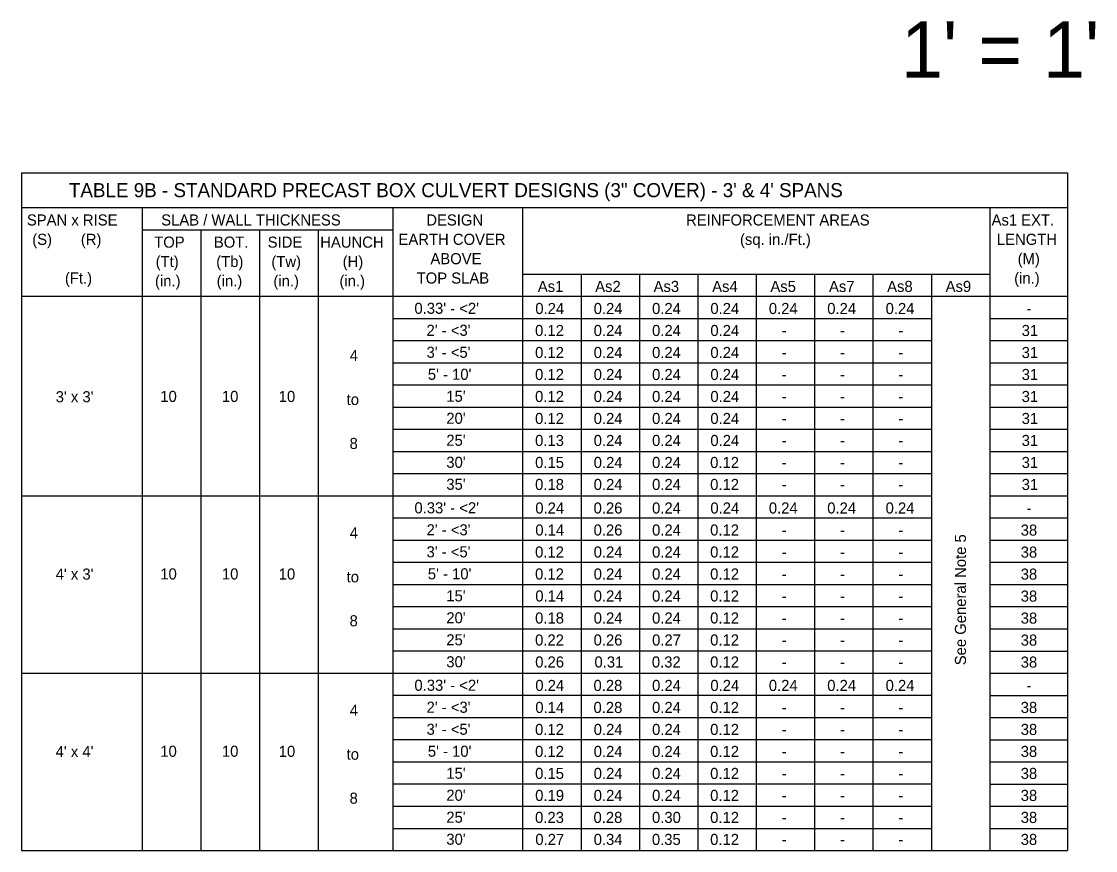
# Model space of a CAD drawing. Extents: x 10338.56 to 10340.78, y 76371.51 to 76372.62.
# Drawn here: x 10339.21 to 10339.821, y 76372.15 to 76372.621 of the extents above; entities that cross this region are included whole.
import ezdxf

# ---------------------------------------------------------------- set-up
doc = ezdxf.new("R2010")
doc.units = 0
doc.layers.add('Border', color=7, linetype='Continuous')
doc.layers.add('SheetBorder_dp', color=7, linetype='Continuous')

msp = doc.modelspace()

# ---------------------------------------------------------------- linework, layer by layer
at = {"layer": 'Border'}
for p, q in [((10339.21023, 76372.53475), (10339.80497, 76372.53475)), ((10339.21023, 76372.53475), (10339.21023, 76372.14953)), ((10339.80497, 76372.53475), (10339.80497, 76372.14953)), ((10339.21023, 76372.51488), (10339.80497, 76372.51488)), ((10339.27886, 76372.51488), (10339.27886, 76372.14958)), ((10339.42131, 76372.51488), (10339.42131, 76372.14958)), ((10339.49519, 76372.51488), (10339.49519, 76372.14958)), ((10339.76078, 76372.51488), (10339.76078, 76372.14958)), ((10339.27886, 76372.50228), (10339.42131, 76372.50228)), ((10339.31222, 76372.50228), (10339.31222, 76372.14958)), ((10339.34558, 76372.50228), (10339.34558, 76372.14958)), ((10339.37895, 76372.50228), (10339.37895, 76372.14958)), ((10339.49519, 76372.47713), (10339.76078, 76372.47713)), ((10339.52839, 76372.47713), (10339.52839, 76372.14958)), ((10339.56158, 76372.47713), (10339.56158, 76372.14958)), ((10339.59478, 76372.47713), (10339.59478, 76372.14958)), ((10339.62798, 76372.47713), (10339.62798, 76372.14958)), ((10339.66118, 76372.47713), (10339.66118, 76372.14958)), ((10339.66118, 76372.47713), (10339.66118, 76372.14958)), ((10339.69438, 76372.47713), (10339.69438, 76372.14958)), ((10339.72758, 76372.47713), (10339.72758, 76372.14958)), ((10339.21023, 76372.46453), (10339.80497, 76372.46453)), ((10339.42131, 76372.45193), (10339.72758, 76372.45193)), ((10339.76078, 76372.45191), (10339.80497, 76372.45191)), ((10339.42131, 76372.43933), (10339.72758, 76372.43933)), ((10339.76078, 76372.43931), (10339.80497, 76372.43931)), ((10339.42131, 76372.42673), (10339.72758, 76372.42673)), ((10339.76078, 76372.42671), (10339.80497, 76372.42671)), ((10339.42131, 76372.41413), (10339.72758, 76372.41413)), ((10339.76078, 76372.41411), (10339.80497, 76372.41411)), ((10339.42131, 76372.40153), (10339.72758, 76372.40153)), ((10339.76078, 76372.40151), (10339.80497, 76372.40151)), ((10339.42131, 76372.38893), (10339.72758, 76372.38893)), ((10339.76078, 76372.38891), (10339.80497, 76372.38891)), ((10339.42131, 76372.37633), (10339.72758, 76372.37633)), ((10339.76078, 76372.37631), (10339.80497, 76372.37631)), ((10339.42131, 76372.36373), (10339.72758, 76372.36373)), ((10339.76078, 76372.36371), (10339.80497, 76372.36371)), ((10339.21023, 76372.35113), (10339.72758, 76372.35113)), ((10339.76078, 76372.35111), (10339.80497, 76372.35111)), ((10339.42131, 76372.33853), (10339.72758, 76372.33853)), ((10339.76078, 76372.33851), (10339.80497, 76372.33851)), ((10339.42131, 76372.32593), (10339.72758, 76372.32593)), ((10339.76078, 76372.32591), (10339.80497, 76372.32591)), ((10339.42131, 76372.31333), (10339.72758, 76372.31333)), ((10339.76078, 76372.31331), (10339.80497, 76372.31331)), ((10339.42131, 76372.30073), (10339.72758, 76372.30073)), ((10339.76078, 76372.30071), (10339.80497, 76372.30071)), ((10339.42131, 76372.28813), (10339.72758, 76372.28813)), ((10339.76078, 76372.28811), (10339.80497, 76372.28811)), ((10339.42131, 76372.27553), (10339.72758, 76372.27553)), ((10339.76078, 76372.27551), (10339.80497, 76372.27551)), ((10339.42131, 76372.26293), (10339.72758, 76372.26293)), ((10339.76078, 76372.26291), (10339.80497, 76372.26291)), ((10339.21023, 76372.25033), (10339.72758, 76372.25033)), ((10339.76078, 76372.25031), (10339.80497, 76372.25031)), ((10339.42131, 76372.23773), (10339.72758, 76372.23773)), ((10339.76078, 76372.23771), (10339.80497, 76372.23771)), ((10339.42131, 76372.22513), (10339.72758, 76372.22513)), ((10339.76078, 76372.22511), (10339.80497, 76372.22511)), ((10339.42131, 76372.21253), (10339.72758, 76372.21253)), ((10339.76078, 76372.21251), (10339.80497, 76372.21251)), ((10339.42131, 76372.19993), (10339.72758, 76372.19993)), ((10339.76078, 76372.19991), (10339.80497, 76372.19991)), ((10339.42131, 76372.18733), (10339.72758, 76372.18733)), ((10339.76078, 76372.18731), (10339.80497, 76372.18731)), ((10339.42131, 76372.17473), (10339.72758, 76372.17473)), ((10339.76078, 76372.17471), (10339.80497, 76372.17471)), ((10339.42131, 76372.16213), (10339.72758, 76372.16213)), ((10339.76078, 76372.16211), (10339.80497, 76372.16211)), ((10339.21023, 76372.14953), (10339.80497, 76372.14953))]:
    msp.add_line(p, q, dxfattribs=at)

# ---------------------------------------------------------------- texts
for s, p in [('SPAN x RISE', (10339.21331, 76372.50472)), ('DESIGN', (10339.44041, 76372.50472)), ('REINFORCEMENT AREAS', (10339.58809, 76372.50472)), ('(S)       (R)', (10339.21636, 76372.49372)), ('(sq. in./Ft.)', (10339.61878, 76372.49372)), ('TOP', (10339.28569, 76372.49212)), ('BOT.', (10339.31962, 76372.49212)), ('SIDE', (10339.35021, 76372.49212)), ('HAUNCH', (10339.3801, 76372.49212)), ('EARTH COVER', (10339.42462, 76372.49372)), ('ABOVE', (10339.44276, 76372.48272)), ('(Tt)', (10339.28653, 76372.48112)), ('(Tb)', (10339.32096, 76372.48112)), ('(Tw)', (10339.35232, 76372.48112)), ('(H)', (10339.39285, 76372.48112)), ('(Ft.)', (10339.23493, 76372.47172)), ('(in.)', (10339.28614, 76372.47012)), ('(in.)', (10339.32123, 76372.47012)), ('(in.)', (10339.35347, 76372.47012)), ('(in.)', (10339.39104, 76372.47012)), ('TOP SLAB', (10339.43493, 76372.47172)), ("0.33' - <2'", (10339.43366, 76372.45452)), ('0.24', (10339.50239, 76372.45441)), ('0.24', (10339.53559, 76372.45441)), ('0.24', (10339.56879, 76372.45441)), ('0.24', (10339.60194, 76372.45441)), ('0.24', (10339.63518, 76372.45441)), ('0.24', (10339.66838, 76372.45441)), ('0.24', (10339.70157, 76372.45441)), ('-', (10339.7817, 76372.45441)), ("2' - <3'", (10339.44056, 76372.44202)), ('0.12', (10339.50226, 76372.44191)), ('0.24', (10339.53559, 76372.44191)), ('0.24', (10339.56879, 76372.44191)), ('0.24', (10339.60194, 76372.44191)), ('31', (10339.77893, 76372.44191)), ('-', (10339.64245, 76372.44191)), ('-', (10339.67566, 76372.44191)), ('-', (10339.70885, 76372.44191)), ('4', (10339.39689, 76372.42773)), ("3' - <5'", (10339.44056, 76372.42952)), ('0.12', (10339.50226, 76372.42941)), ('0.24', (10339.53559, 76372.42941)), ('0.24', (10339.56879, 76372.42941)), ('0.24', (10339.60194, 76372.42941)), ('31', (10339.77893, 76372.42941)), ('-', (10339.64245, 76372.42941)), ('-', (10339.67566, 76372.42941)), ('-', (10339.70885, 76372.42941)), ("5' - 10'", (10339.44128, 76372.41702)), ('0.12', (10339.50226, 76372.41691)), ('0.24', (10339.53559, 76372.41691)), ('0.24', (10339.56879, 76372.41691)), ('0.24', (10339.60194, 76372.41691)), ('31', (10339.77893, 76372.41691)), ('-', (10339.64245, 76372.41691)), ('-', (10339.67566, 76372.41691)), ('-', (10339.70885, 76372.41691)), ('10', (10339.28917, 76372.40446)), ('10', (10339.32421, 76372.40446)), ('10', (10339.3565, 76372.40441)), ("15'", (10339.45179, 76372.40452)), ('0.12', (10339.50226, 76372.40441)), ('0.24', (10339.53559, 76372.40441)), ('0.24', (10339.56879, 76372.40441)), ('0.24', (10339.60194, 76372.40441)), ('31', (10339.77893, 76372.40441)), ('to', (10339.39511, 76372.40273)), ('-', (10339.64245, 76372.40441)), ('-', (10339.67566, 76372.40441)), ('-', (10339.70885, 76372.40441)), ("20'", (10339.45179, 76372.39202)), ('0.12', (10339.50226, 76372.39191)), ('0.24', (10339.53559, 76372.39191)), ('0.24', (10339.56879, 76372.39191)), ('0.24', (10339.60194, 76372.39191)), ('31', (10339.77893, 76372.39191)), ('-', (10339.64245, 76372.39191)), ('-', (10339.67566, 76372.39191)), ('-', (10339.70885, 76372.39191)), ("25'", (10339.45179, 76372.37952)), ('0.13', (10339.50226, 76372.37941)), ('0.24', (10339.53559, 76372.37941)), ('0.24', (10339.56879, 76372.37941)), ('0.24', (10339.60194, 76372.37941)), ('31', (10339.77893, 76372.37941)), ('8', (10339.39678, 76372.37773)), ('-', (10339.64245, 76372.37941)), ('-', (10339.67566, 76372.37941)), ('-', (10339.70885, 76372.37941)), ("30'", (10339.45179, 76372.36702)), ('0.15', (10339.50229, 76372.36691)), ('0.24', (10339.53559, 76372.36691)), ('0.24', (10339.56879, 76372.36691)), ('0.12', (10339.60182, 76372.36691)), ('31', (10339.77893, 76372.36691)), ('-', (10339.64245, 76372.36691)), ('-', (10339.67566, 76372.36691)), ('-', (10339.70885, 76372.36691)), ("35'", (10339.45179, 76372.35452)), ('0.18', (10339.50228, 76372.35441)), ('0.24', (10339.53559, 76372.35441)), ('0.24', (10339.56879, 76372.35441)), ('0.12', (10339.60182, 76372.35441)), ('31', (10339.77893, 76372.35441)), ('-', (10339.64245, 76372.35441)), ('-', (10339.67566, 76372.35441)), ('-', (10339.70885, 76372.35441)), ("0.33' - <2'", (10339.43366, 76372.34113)), ('0.24', (10339.50239, 76372.34103)), ('0.26', (10339.53553, 76372.34103)), ('0.24', (10339.56879, 76372.34103)), ('0.24', (10339.60194, 76372.34103)), ('0.24', (10339.63518, 76372.34103)), ('0.24', (10339.66838, 76372.34103)), ('0.24', (10339.70157, 76372.34103)), ('-', (10339.7817, 76372.34097)), ('4', (10339.39689, 76372.32693)), ("2' - <3'", (10339.44056, 76372.32863)), ('0.14', (10339.50239, 76372.32853)), ('0.26', (10339.53553, 76372.32853)), ('0.24', (10339.56879, 76372.32853)), ('0.12', (10339.60182, 76372.32853)), ('-', (10339.64245, 76372.32853)), ('-', (10339.67566, 76372.32853)), ('-', (10339.70885, 76372.32853)), ('38', (10339.77839, 76372.32847)), ("3' - <5'", (10339.44056, 76372.31613)), ('0.12', (10339.50226, 76372.31603)), ('0.24', (10339.53559, 76372.31603)), ('0.24', (10339.56879, 76372.31603)), ('0.12', (10339.60182, 76372.31603)), ('-', (10339.64245, 76372.31603)), ('-', (10339.67566, 76372.31603)), ('-', (10339.70885, 76372.31603)), ('38', (10339.77839, 76372.31597)), ('10', (10339.28917, 76372.30358)), ('10', (10339.32421, 76372.30358)), ('10', (10339.3565, 76372.30353)), ('to', (10339.39511, 76372.30193)), ("5' - 10'", (10339.44128, 76372.30363)), ('0.12', (10339.50226, 76372.30353)), ('0.24', (10339.53559, 76372.30353)), ('0.24', (10339.56879, 76372.30353)), ('0.12', (10339.60182, 76372.30353)), ('-', (10339.64245, 76372.30353)), ('-', (10339.67566, 76372.30353)), ('-', (10339.70885, 76372.30353)), ('38', (10339.77839, 76372.30347)), ("15'", (10339.45179, 76372.29113)), ('0.14', (10339.50239, 76372.29103)), ('0.24', (10339.53559, 76372.29103)), ('0.24', (10339.56879, 76372.29103)), ('0.12', (10339.60182, 76372.29103)), ('-', (10339.64245, 76372.29103)), ('-', (10339.67566, 76372.29103)), ('-', (10339.70885, 76372.29103)), ('38', (10339.77839, 76372.29097)), ('8', (10339.39678, 76372.27693)), ("20'", (10339.45179, 76372.27863)), ('0.18', (10339.50228, 76372.27853)), ('0.24', (10339.53559, 76372.27853)), ('0.24', (10339.56879, 76372.27853)), ('0.12', (10339.60182, 76372.27853)), ('-', (10339.64245, 76372.27853)), ('-', (10339.67566, 76372.27853)), ('-', (10339.70885, 76372.27853)), ('38', (10339.77839, 76372.27847)), ("25'", (10339.45179, 76372.26613)), ('0.22', (10339.50226, 76372.26603)), ('0.26', (10339.53553, 76372.26603)), ('0.27', (10339.5688, 76372.26603)), ('0.12', (10339.60182, 76372.26603)), ('-', (10339.64245, 76372.26603)), ('-', (10339.67566, 76372.26603)), ('-', (10339.70885, 76372.26603)), ('38', (10339.77839, 76372.26597)), ("30'", (10339.45179, 76372.25363)), ('0.26', (10339.50233, 76372.25353)), ('0.31', (10339.53603, 76372.25353)), ('0.32', (10339.56866, 76372.25353)), ('0.12', (10339.60182, 76372.25353)), ('-', (10339.64245, 76372.25353)), ('-', (10339.67566, 76372.25353)), ('-', (10339.70885, 76372.25353)), ('38', (10339.77839, 76372.25347)), ("0.33' - <2'", (10339.43366, 76372.2403)), ('0.24', (10339.50239, 76372.24019)), ('0.28', (10339.53548, 76372.24019)), ('0.24', (10339.56879, 76372.24019)), ('0.24', (10339.60194, 76372.24019)), ('0.24', (10339.63518, 76372.24019)), ('0.24', (10339.66838, 76372.24019)), ('0.24', (10339.70157, 76372.24019)), ('-', (10339.7817, 76372.24019)), ('4', (10339.39689, 76372.22613)), ("2' - <3'", (10339.44056, 76372.2278)), ('0.14', (10339.50239, 76372.22769)), ('0.28', (10339.53548, 76372.22769)), ('0.24', (10339.56879, 76372.22769)), ('0.12', (10339.60182, 76372.22769)), ('38', (10339.77839, 76372.22769)), ('-', (10339.64245, 76372.22769)), ('-', (10339.67566, 76372.22769)), ('-', (10339.70885, 76372.22769)), ("3' - <5'", (10339.44056, 76372.2153)), ('0.12', (10339.50226, 76372.21519)), ('0.24', (10339.53559, 76372.21519)), ('0.24', (10339.56879, 76372.21519)), ('0.12', (10339.60182, 76372.21519)), ('38', (10339.77839, 76372.21519)), ('-', (10339.64245, 76372.21519)), ('-', (10339.67566, 76372.21519)), ('-', (10339.70885, 76372.21519)), ('10', (10339.28917, 76372.2028)), ('10', (10339.32421, 76372.2028)), ('10', (10339.3565, 76372.20275)), ("5' - 10'", (10339.44128, 76372.2028)), ('0.12', (10339.50226, 76372.20269)), ('0.24', (10339.53559, 76372.20269)), ('0.24', (10339.56879, 76372.20269)), ('0.12', (10339.60182, 76372.20269)), ('38', (10339.77839, 76372.20269)), ('to', (10339.39511, 76372.20113)), ('-', (10339.64245, 76372.20269)), ('-', (10339.67566, 76372.20269)), ('-', (10339.70885, 76372.20269)), ("15'", (10339.45179, 76372.1903)), ('0.15', (10339.50229, 76372.19019)), ('0.24', (10339.53559, 76372.19019)), ('0.24', (10339.56879, 76372.19019)), ('0.12', (10339.60182, 76372.19019)), ('38', (10339.77839, 76372.19019)), ('-', (10339.64245, 76372.19019)), ('-', (10339.67566, 76372.19019)), ('-', (10339.70885, 76372.19019)), ("20'", (10339.45179, 76372.1778)), ('0.19', (10339.50233, 76372.17769)), ('0.24', (10339.53559, 76372.17769)), ('0.24', (10339.56879, 76372.17769)), ('0.12', (10339.60182, 76372.17769)), ('38', (10339.77839, 76372.17769)), ('8', (10339.39678, 76372.17613)), ('-', (10339.64245, 76372.17769)), ('-', (10339.67566, 76372.17769)), ('-', (10339.70885, 76372.17769)), ("25'", (10339.45179, 76372.1653)), ('0.23', (10339.50226, 76372.16519)), ('0.28', (10339.53548, 76372.16519)), ('0.30', (10339.56874, 76372.16519)), ('0.12', (10339.60182, 76372.16519)), ('38', (10339.77839, 76372.16519)), ('-', (10339.64245, 76372.16519)), ('-', (10339.67566, 76372.16519)), ('-', (10339.70885, 76372.16519)), ("30'", (10339.45179, 76372.1528)), ('0.27', (10339.5024, 76372.15269)), ('0.34', (10339.53559, 76372.15269)), ('0.35', (10339.56869, 76372.15269)), ('0.12', (10339.60182, 76372.15269)), ('38', (10339.77839, 76372.15269)), ('-', (10339.64245, 76372.15269)), ('-', (10339.67566, 76372.15269)), ('-', (10339.70885, 76372.15269))]:
    msp.add_text(s, height=0.0063, dxfattribs=at).set_placement(p)
for s, p in [('As1 EXT.', (10339.76182, 76372.50472)), ('LENGTH', (10339.76485, 76372.49372)), ('(M)', (10339.77665, 76372.48272)), ('(in.)', (10339.77469, 76372.47172))]:
    msp.add_text(s, height=0.0063, rotation=360, dxfattribs=at).set_placement(p)
at = {"layer": 'SheetBorder_dp'}
for s, height, p in [("1' = 1'", 0.032, (10339.71037, 76372.58867)), ('TABLE 9B - STANDARD PRECAST BOX CULVERT DESIGNS (3" COVER) - 3\' & 4\' SPANS', 0.008, (10339.23719, 76372.52082)), ('SLAB / WALL THICKNESS', 0.0063, (10339.28968, 76372.50472)), ('As1', 0.0063, (10339.50381, 76372.46696)), ('As2', 0.0063, (10339.53644, 76372.46696)), ('As3', 0.0063, (10339.56963, 76372.46696)), ('As4', 0.0063, (10339.60296, 76372.46696)), ('As5', 0.0063, (10339.63606, 76372.46696)), ('As7', 0.0063, (10339.6694, 76372.46696)), ('As8', 0.0063, (10339.70245, 76372.46696)), ('As9', 0.0063, (10339.7357, 76372.46696)), ("3' x 3'", 0.0063, (10339.22969, 76372.40425)), ("4' x 3'", 0.0063, (10339.22968, 76372.30347)), ("4' x 4'", 0.0063, (10339.22967, 76372.20264))]:
    msp.add_text(s, height=height, dxfattribs=at).set_placement(p)
msp.add_text('See General Note 5', height=0.0063, rotation=90, dxfattribs=at).set_placement((10339.74728, 76372.25481))

doc.saveas('drawing.dxf')
